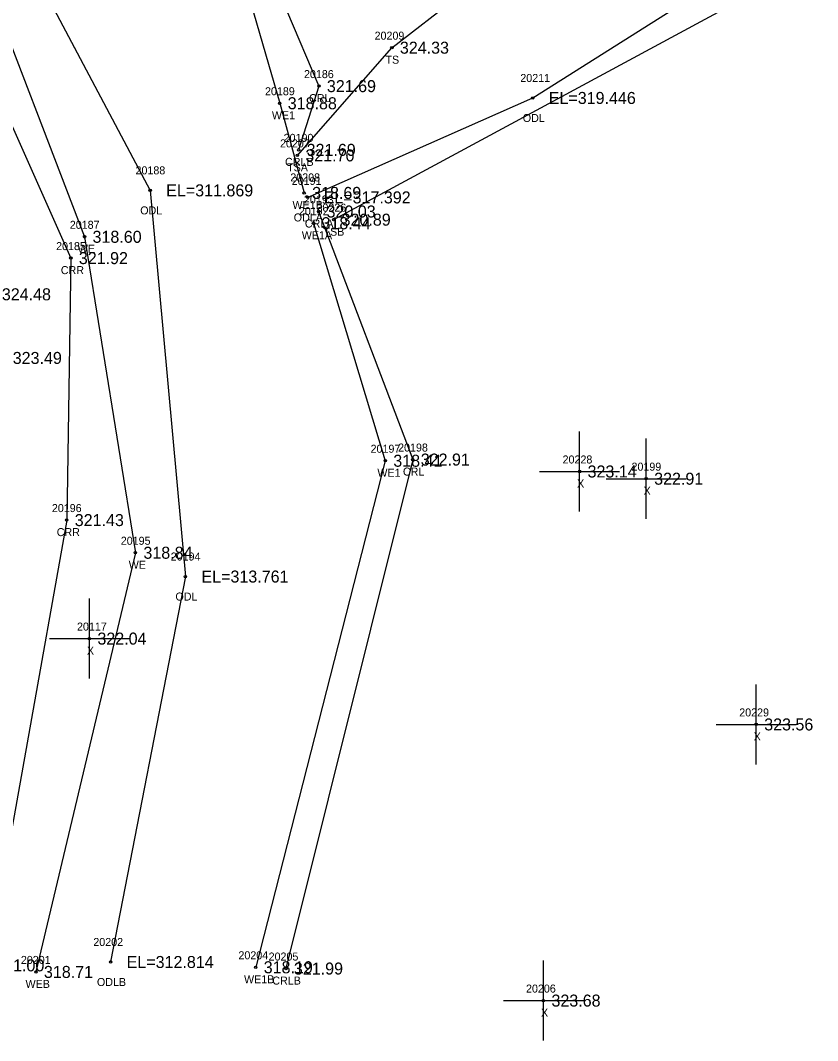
# Model space of a CAD drawing. Extents: x 2231109 to 2232328, y 1035718 to 1036919.
# Drawn here: x 2231559.2 to 2231658.8, y 1036320.4 to 1036447.8 of the extents above; entities that cross this region are included whole.
import ezdxf

# ---------------------------------------------------------------- set-up
doc = ezdxf.new("R2010")
doc.units = 0
for name, color, linetype in [('RD_DTM_BkLn2', 7, 'Continuous'), ('RD_DTM_BkLn_txCode', 7, 'Continuous'), ('RD_EX_H2O', 7, 'Continuous'), ('RD_EX_H2O_txCode', 7, 'Continuous'), ('RD_EX_Misc', 7, 'Continuous'), ('RD_EX_Misc_txCode', 7, 'Continuous'), ('RD_EX_TX_H2O_ELEV', 7, 'Continuous'), ('RD_EX_TX_Misc_ELEV', 7, 'Continuous'), ('RD_SMD_Locator', 7, 'Continuous')]:
    doc.layers.add(name, color=color, linetype=linetype)

msp = doc.modelspace()

# ---------------------------------------------------------------- linework, layer by layer
at = {"layer": 'RD_DTM_BkLn2'}
msp.add_lwpolyline([(2231593.79, 1036430.95), (2231605.6, 1036444.4), (2231613.9, 1036450.83), (2231692.8, 1036494.19), (2231698.97, 1036489.96), (2231701.87, 1036483.3), (2231696.9, 1036476.1), (2231598.32, 1036422.92)], dxfattribs=at)
at = {"layer": 'RD_EX_H2O'}
for points in [[(2231502.13, 1036543.02), (2231534.56, 1036503.52), (2231575.4, 1036426.58), (2231579.81, 1036378.35), (2231570.46, 1036330.21)], [(2231595.07, 1036425.7), (2231623.2, 1036438.12), (2231694.44, 1036483.11)], [(2231576.03, 1036469.55), (2231583.32, 1036466.02), (2231591.59, 1036437.46), (2231594.64, 1036426.26)], [(2231578.53, 1036469.5), (2231584.36, 1036468.09), (2231596.48, 1036439.6), (2231593.95, 1036431.64)], [(2231554.2, 1036454.63), (2231567.2, 1036420.78), (2231573.56, 1036381.32), (2231561.13, 1036328.97)], [(2231550.29, 1036452.23), (2231565.49, 1036418.12), (2231564.98, 1036385.4), (2231555.04, 1036329.79)], [(2231596.44, 1036423.94), (2231608.21, 1036392.96), (2231592.36, 1036329.39)], [(2231595.81, 1036422.48), (2231604.78, 1036392.81), (2231588.59, 1036329.55)]]:
    msp.add_lwpolyline(points, dxfattribs=at)
at = {"layer": 'RD_EX_Misc'}
for p, q in [((2231629.05, 1036386.47), (2231629.05, 1036396.47)), ((2231637.37, 1036385.57), (2231637.37, 1036395.57)), ((2231624.05, 1036391.47), (2231634.05, 1036391.47)), ((2231632.37, 1036390.57), (2231642.37, 1036390.57)), ((2231567.81, 1036365.6), (2231567.81, 1036375.6)), ((2231562.81, 1036370.6), (2231572.81, 1036370.6)), ((2231651.12, 1036354.88), (2231651.12, 1036364.88)), ((2231646.12, 1036359.88), (2231656.12, 1036359.88)), ((2231624.54, 1036320.39), (2231624.54, 1036330.39)), ((2231619.54, 1036325.39), (2231629.54, 1036325.39))]:
    msp.add_line(p, q, dxfattribs=at)
at = {"layer": 'RD_SMD_Locator'}
for centre in [(2231605.6, 1036444.4), (2231596.48, 1036439.6), (2231623.2, 1036438.12), (2231591.59, 1036437.46), (2231593.79, 1036430.95), (2231593.95, 1036431.64), (2231575.4, 1036426.58), (2231594.64, 1036426.26), (2231595.07, 1036425.7), (2231596.44, 1036423.94), (2231598.32, 1036422.92), (2231595.81, 1036422.48), (2231567.2, 1036420.78), (2231565.49, 1036418.12), (2231604.78, 1036392.81), (2231608.21, 1036392.96), (2231629.05, 1036391.47), (2231637.37, 1036390.57), (2231564.98, 1036385.4), (2231573.56, 1036381.32), (2231579.81, 1036378.35), (2231567.81, 1036370.6), (2231651.12, 1036359.88), (2231570.46, 1036330.21), (2231561.13, 1036328.97), (2231588.59, 1036329.55), (2231592.36, 1036329.39), (2231624.54, 1036325.39)]:
    msp.add_circle(centre, 0.15, dxfattribs=at)

# ---------------------------------------------------------------- texts
at = {"layer": 'RD_DTM_BkLn_txCode'}
for s, p in [('20209', (2231603.44, 1036445.4)), ('TS', (2231604.8, 1036442.4)), ('20207', (2231591.63, 1036431.95)), ('TSA', (2231592.51, 1036428.95)), ('20226', (2231596.18, 1036423.92)), ('TSB', (2231597.06, 1036420.92))]:
    msp.add_text(s, height=1, dxfattribs=at).set_placement(p)
at = {"layer": 'RD_EX_H2O_txCode'}
for s, p in [('20186', (2231594.62, 1036440.6)), ('20211', (2231621.65, 1036440.12)), ('20189', (2231589.75, 1036438.46)), ('CRL', (2231595.25, 1036437.6)), ('WE1', (2231590.61, 1036435.46)), ('ODL', (2231621.96, 1036435.12)), ('20190', (2231592.08, 1036432.64)), ('CRLB', (2231592.25, 1036429.64)), ('20188', (2231573.57, 1036428.58)), ('20208', (2231592.91, 1036427.7)), ('20191', (2231593.09, 1036427.26)), ('20193', (2231594.61, 1036424.94)), ('ODL', (2231574.16, 1036423.58)), ('WE1B', (2231593.18, 1036424.26)), ('20192', (2231593.98, 1036423.48)), ('ODLA', (2231593.34, 1036422.7)), ('CRLA', (2231594.73, 1036421.94)), ('20187', (2231565.36, 1036421.78)), ('WE1A', (2231594.34, 1036420.48)), ('20185', (2231563.65, 1036419.12)), ('WE', (2231566.36, 1036418.78)), ('CRR', (2231564.24, 1036416.12)), ('20198', (2231606.38, 1036393.96)), ('20197', (2231602.94, 1036393.81)), ('WE1', (2231603.79, 1036390.81)), ('CRL', (2231606.98, 1036390.96)), ('20196', (2231563.12, 1036386.4)), ('CRR', (2231563.73, 1036383.4)), ('20195', (2231571.73, 1036382.32)), ('20194', (2231577.97, 1036380.35)), ('WE', (2231572.72, 1036379.32)), ('ODL', (2231578.56, 1036375.35)), ('20202', (2231568.3, 1036332.21)), ('20204', (2231586.43, 1036330.55)), ('20205', (2231590.2, 1036330.39)), ('20201', (2231559.25, 1036329.97)), ('WEB', (2231559.83, 1036326.97)), ('ODLB', (2231568.75, 1036327.21)), ('WE1B', (2231587.13, 1036327.55)), ('CRLB', (2231590.66, 1036327.39))]:
    msp.add_text(s, height=1, dxfattribs=at).set_placement(p)
at = {"layer": 'RD_EX_Misc_txCode'}
for s, p in [('20228', (2231626.93, 1036392.47)), ('20199', (2231635.54, 1036391.57)), ('X', (2231628.74, 1036389.47)), ('X', (2231637.05, 1036388.57)), ('20117', (2231566.26, 1036371.6)), ('X', (2231567.5, 1036368.6)), ('20229', (2231649, 1036360.88)), ('X', (2231650.81, 1036357.88)), ('20206', (2231622.36, 1036326.39)), ('X', (2231624.23, 1036323.39))]:
    msp.add_text(s, height=1, dxfattribs=at).set_placement(p)
at = {"layer": 'RD_EX_TX_H2O_ELEV'}
for s, p in [('321.69', (2231597.48, 1036438.85)), ('EL=319.446', (2231625.2, 1036437.37)), ('318.88', (2231592.59, 1036436.71)), ('321.69', (2231594.95, 1036430.89)), ('EL=311.869', (2231577.4, 1036425.83)), ('318.69', (2231595.64, 1036425.51)), ('EL=317.392', (2231597.07, 1036424.95)), ('320.03', (2231597.44, 1036423.19)), ('318.44', (2231596.81, 1036421.73)), ('318.60', (2231568.2, 1036420.03)), ('321.92', (2231566.49, 1036417.37)), ('322.91', (2231609.21, 1036392.21)), ('318.41', (2231605.78, 1036392.06)), ('321.43', (2231565.98, 1036384.65)), ('318.84', (2231574.56, 1036380.57)), ('EL=313.761', (2231581.81, 1036377.6)), ('321.00', (2231556.04, 1036329.04)), ('EL=312.814', (2231572.46, 1036329.46)), ('318.19', (2231589.59, 1036328.8)), ('321.99', (2231593.36, 1036328.64)), ('318.71', (2231562.13, 1036328.22))]:
    msp.add_text(s, height=1.5, dxfattribs=at).set_placement(p)
at = {"layer": 'RD_EX_TX_Misc_ELEV'}
for s, p in [('324.33', (2231606.6, 1036443.65)), ('321.70', (2231594.79, 1036430.2)), ('320.89', (2231599.32, 1036422.17)), ('324.48', (2231556.87, 1036412.85)), ('323.49', (2231558.23, 1036404.9)), ('323.14', (2231630.05, 1036390.72)), ('322.91', (2231638.37, 1036389.82)), ('322.04', (2231568.81, 1036369.85)), ('323.56', (2231652.12, 1036359.13)), ('323.68', (2231625.54, 1036324.64))]:
    msp.add_text(s, height=1.5, dxfattribs=at).set_placement(p)

doc.saveas('drawing.dxf')
